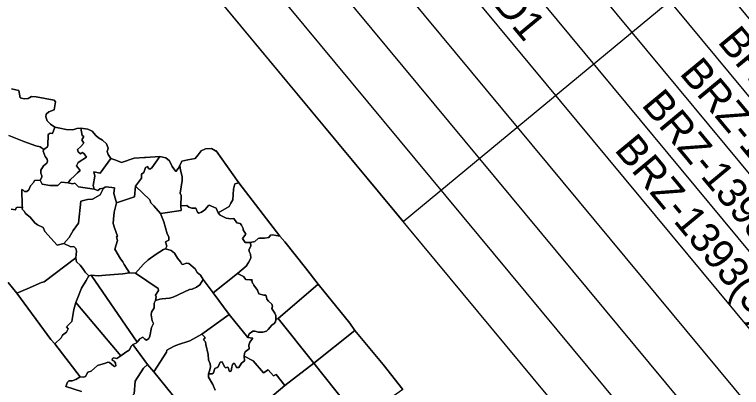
# Model space of a CAD drawing. Extents: x 2054826 to 2060231, y 685508 to 690809.
# Drawn here: x 2059671.1 to 2059946.5, y 688368.3 to 688509.7 of the extents above; entities that cross this region are included whole.
import ezdxf

# ---------------------------------------------------------------- set-up
doc = ezdxf.new("R2010")
doc.units = 0
for name, color, linetype in [('Old_Level_1', 7, 'Continuous'), ('Sheet Data Field CELL', 7, 'Continuous'), ('Sheet Title CELL', 7, 'Continuous')]:
    doc.layers.add(name, color=color, linetype=linetype)

msp = doc.modelspace()

# ---------------------------------------------------------------- linework, layer by layer
at = {"layer": 'Old_Level_1'}
for points in [[(2059818.23, 688367.63), (2059810.84, 688376.99), (2059800.09, 688389.92), (2059798.1, 688392.71), (2059786.18, 688407.48), (2059781.34, 688413.68), (2059773.48, 688423.55), (2059771.69, 688425.65), (2059756.11, 688445.98), (2059747.56, 688458.07), (2059747.29, 688458.09), (2059745.8, 688458.95), (2059743.52, 688458.8), (2059741.81, 688458.03), (2059740.71, 688456.55), (2059739.52, 688455.21), (2059736.76, 688454.59), (2059734.58, 688454.14), (2059733.76, 688452.5), (2059733.12, 688451.4), (2059732.19, 688450.21), (2059730.88, 688452.06), (2059729.91, 688454.21), (2059728.48, 688455.38), (2059726.15, 688455.9), (2059720.72, 688455.49), (2059720.35, 688455.53), (2059716.49, 688455.28), (2059711.71, 688453.68), (2059709.46, 688454.5), (2059707.59, 688455.12), (2059706.58, 688456.62), (2059706.3, 688457.77), (2059706.64, 688459.04), (2059706.04, 688460.71), (2059704.46, 688462.12), (2059702.91, 688462.94), (2059701.94, 688463.93), (2059700.61, 688465.5), (2059698.89, 688466.29), (2059696.2, 688466.66), (2059694.77, 688466.58), (2059693.19, 688466.03), (2059690.67, 688466.15), (2059688.34, 688466.66), (2059686.47, 688467), (2059684.74, 688468.22), (2059683.51, 688469.49), (2059682.96, 688470.92), (2059683.15, 688472.01), (2059684.14, 688472.8), (2059686.22, 688473.66), (2059686.61, 688476.66), (2059686.21, 688477.29), (2059679.29, 688478.55), (2059677.54, 688478.69), (2059676.28, 688477.91), (2059674.83, 688477.71), (2059673.31, 688478.18), (2059672.72, 688480.91), (2059671.59, 688481.18), (2059670, 688481.6)], [(2059670, 688481.6), (2059671.59, 688481.18), (2059672.72, 688480.91), (2059673.31, 688478.18), (2059674.83, 688477.71), (2059676.28, 688477.91), (2059677.54, 688478.69), (2059679.29, 688478.55)], [(2059679.29, 688478.55), (2059686.21, 688477.29), (2059686.61, 688476.66), (2059686.22, 688473.66), (2059684.14, 688472.8), (2059683.15, 688472.01), (2059682.96, 688470.92), (2059683.51, 688469.49), (2059684.74, 688468.22), (2059686.47, 688467), (2059685.57, 688464.67), (2059684.62, 688464.79), (2059683.95, 688464.19), (2059683.8, 688460.12), (2059683.62, 688459.57), (2059682.19, 688458.5), (2059680.91, 688459.56), (2059679.21, 688459.92), (2059674.73, 688461.63), (2059668.93, 688463.93)], [(2059696.2, 688466.66), (2059696.78, 688463.92), (2059697.46, 688463.54), (2059696.68, 688462.27), (2059697.41, 688460.95), (2059696.12, 688459.53), (2059695.01, 688458.5), (2059695.3, 688457.62), (2059696.13, 688456.98), (2059696.93, 688457.39), (2059697.58, 688456.9), (2059698.38, 688455.62), (2059695.23, 688453.68), (2059694.66, 688452.36), (2059696.06, 688450.66), (2059694.98, 688449.73), (2059693.9, 688448.53), (2059692.4, 688447.17), (2059691.41, 688445.95), (2059688.86, 688446.14), (2059687.49, 688444.85), (2059684.52, 688444.86), (2059681.67, 688445.39), (2059680.82, 688446.89), (2059681.53, 688448.13), (2059681.48, 688448.62), (2059681.11, 688449.63), (2059681.1, 688450.77), (2059682.07, 688452.42), (2059683.41, 688453.34), (2059683.59, 688454.17), (2059683.55, 688454.93), (2059682.79, 688455.87), (2059682.05, 688457.89), (2059682.19, 688458.5), (2059683.62, 688459.57), (2059683.8, 688460.12), (2059683.95, 688464.19), (2059684.62, 688464.79), (2059685.57, 688464.67), (2059686.47, 688467), (2059688.34, 688466.66), (2059690.67, 688466.15), (2059693.19, 688466.03), (2059694.77, 688466.58), (2059696.2, 688466.66)], [(2059701.26, 688443.55), (2059695.44, 688444.37), (2059694.03, 688445.8), (2059693.16, 688445.52), (2059691.41, 688445.95), (2059692.4, 688447.17), (2059693.9, 688448.53), (2059694.98, 688449.73), (2059696.06, 688450.66), (2059694.66, 688452.36), (2059695.23, 688453.68), (2059698.38, 688455.62), (2059697.58, 688456.9), (2059696.93, 688457.39), (2059696.13, 688456.98), (2059695.3, 688457.62), (2059695.01, 688458.5), (2059696.12, 688459.53), (2059697.41, 688460.95), (2059696.68, 688462.27), (2059697.46, 688463.54), (2059696.78, 688463.92), (2059696.2, 688466.66), (2059698.89, 688466.29), (2059700.61, 688465.5), (2059701.94, 688463.93), (2059702.91, 688462.94), (2059704.46, 688462.12), (2059706.04, 688460.71), (2059706.64, 688459.04), (2059706.3, 688457.77), (2059706.58, 688456.62), (2059707.59, 688455.12), (2059703.58, 688449.65), (2059701.13, 688450.08), (2059701.58, 688448.51), (2059700.97, 688444.86), (2059701.26, 688443.55)], [(2059668.93, 688463.93), (2059674.73, 688461.63), (2059679.21, 688459.92), (2059680.91, 688459.56)], [(2059680.91, 688459.56), (2059682.19, 688458.5), (2059682.05, 688457.89), (2059682.79, 688455.87), (2059683.55, 688454.93), (2059683.59, 688454.17), (2059683.41, 688453.34), (2059682.07, 688452.42), (2059681.1, 688450.77), (2059681.11, 688449.63), (2059681.48, 688448.62), (2059681.53, 688448.13), (2059680.82, 688446.89), (2059678.74, 688446.75), (2059678.45, 688446.22), (2059677.23, 688444.84), (2059676.59, 688443.22), (2059675.86, 688442.59), (2059674.95, 688442.64), (2059674.43, 688443.2), (2059673.88, 688443.39), (2059674.01, 688437.32), (2059674.22, 688436.57), (2059672.21, 688436.73), (2059671.81, 688436.4), (2059671.49, 688435.67), (2059669.87, 688435.9)], [(2059756.11, 688445.98), (2059754.64, 688445.53), (2059754.15, 688443.47), (2059753.81, 688439.46), (2059753.11, 688438.16), (2059752.49, 688436.89), (2059748.33, 688434.56), (2059747.5, 688436.35), (2059744.92, 688437.44), (2059744.56, 688437.31), (2059743.2, 688435.69), (2059741.94, 688434.76), (2059740.93, 688434.4), (2059740.47, 688434.74), (2059739.81, 688436.38), (2059738.32, 688436.26), (2059737.21, 688436.65), (2059736.44, 688437.33), (2059734.17, 688437.19), (2059734.28, 688441.14), (2059733.87, 688441.95), (2059734.66, 688446.76), (2059734.65, 688448.35), (2059733.96, 688450.76), (2059733.76, 688452.5), (2059734.58, 688454.14), (2059736.76, 688454.59), (2059739.52, 688455.21), (2059740.71, 688456.55), (2059741.81, 688458.03), (2059743.52, 688458.8), (2059745.8, 688458.95), (2059747.29, 688458.09), (2059747.56, 688458.07), (2059756.11, 688445.98)], [(2059717.03, 688444.66), (2059716.54, 688440.65), (2059709.77, 688438.37), (2059708.96, 688440.95), (2059708.8, 688441.91), (2059709.03, 688444.08), (2059705.92, 688444.46), (2059705.54, 688444.23), (2059704.87, 688443.91), (2059703.52, 688443.7), (2059702.65, 688442.99), (2059701.26, 688443.55), (2059700.97, 688444.86), (2059701.58, 688448.51), (2059701.13, 688450.08), (2059703.58, 688449.65), (2059707.59, 688455.12), (2059709.46, 688454.5), (2059711.71, 688453.68), (2059716.49, 688455.28), (2059720.35, 688455.53), (2059720.72, 688455.49), (2059726.15, 688455.9), (2059723.1, 688451.64), (2059722.42, 688451.05), (2059721.75, 688451.43), (2059721.62, 688452.06), (2059720.74, 688451.79), (2059720.09, 688449.88), (2059719.22, 688449.18), (2059719.19, 688447.66), (2059717.03, 688444.66)], [(2059733.76, 688452.5), (2059733.96, 688450.76), (2059734.65, 688448.35), (2059734.66, 688446.76), (2059733.87, 688441.95), (2059734.28, 688441.14), (2059734.17, 688437.19), (2059734.26, 688435.48), (2059726.47, 688434.28), (2059723.96, 688437.24), (2059722.81, 688438.39), (2059722.41, 688439.47), (2059717.03, 688444.66), (2059719.19, 688447.66), (2059719.22, 688449.18), (2059720.09, 688449.88), (2059720.74, 688451.79), (2059721.62, 688452.06), (2059721.75, 688451.43), (2059722.42, 688451.05), (2059723.1, 688451.64), (2059726.15, 688455.9), (2059728.48, 688455.38), (2059729.91, 688454.21), (2059730.88, 688452.06), (2059732.19, 688450.21), (2059733.12, 688451.4), (2059733.76, 688452.5)], [(2059703.52, 688443.7), (2059704.87, 688443.91), (2059703.64, 688441.39), (2059700.66, 688439.74), (2059698.84, 688439.59), (2059696.2, 688438.94), (2059695.32, 688430.67), (2059693.37, 688427.8), (2059691.85, 688425.2), (2059689.77, 688422.96), (2059687.34, 688422.27), (2059682.62, 688427.52), (2059682.04, 688429.01), (2059679.89, 688429.97), (2059678.84, 688430.82), (2059677.05, 688432.87), (2059675.31, 688434.26), (2059674.82, 688435.18), (2059674.08, 688435.95), (2059674.22, 688436.57), (2059674.01, 688437.32), (2059673.88, 688443.39), (2059674.43, 688443.2), (2059674.95, 688442.64), (2059675.86, 688442.59), (2059676.59, 688443.22), (2059677.23, 688444.84), (2059678.45, 688446.22), (2059678.74, 688446.75), (2059680.82, 688446.89), (2059681.67, 688445.39), (2059684.52, 688444.86), (2059687.49, 688444.85), (2059688.86, 688446.14), (2059691.41, 688445.95), (2059693.16, 688445.52), (2059694.03, 688445.8), (2059695.44, 688444.37), (2059701.26, 688443.55), (2059702.65, 688442.99), (2059703.52, 688443.7)], [(2059709.77, 688438.37), (2059708.9, 688434.84), (2059708.66, 688432.14), (2059708.5, 688430.55), (2059708.99, 688428.91), (2059710.13, 688425.65), (2059709.81, 688425.46), (2059710.14, 688424.08), (2059709.08, 688420.72), (2059711.28, 688417.14), (2059712.19, 688415.93), (2059712.65, 688414.9), (2059713.8, 688413.15), (2059714.73, 688411.78), (2059712.2, 688411.39), (2059705.59, 688410.88), (2059702.84, 688410.7), (2059700.2, 688410.93), (2059699.32, 688410.66), (2059697.86, 688412.05), (2059697.28, 688413.01), (2059695.96, 688414.74), (2059694.61, 688415.94), (2059694.33, 688417.52), (2059694.59, 688420.04), (2059694.4, 688421.06), (2059693.64, 688421.74), (2059692.42, 688421.61), (2059689.77, 688422.96), (2059691.85, 688425.2), (2059693.37, 688427.8), (2059695.32, 688430.67), (2059696.2, 688438.94), (2059698.84, 688439.59), (2059700.66, 688439.74), (2059703.64, 688441.39), (2059704.87, 688443.91), (2059705.54, 688444.23), (2059705.92, 688444.46), (2059709.03, 688444.08), (2059708.8, 688441.91), (2059708.96, 688440.95), (2059709.77, 688438.37)], [(2059716.97, 688411.65), (2059714.73, 688411.78), (2059713.8, 688413.15), (2059712.65, 688414.9), (2059712.19, 688415.93), (2059711.28, 688417.14), (2059709.08, 688420.72), (2059710.14, 688424.08), (2059709.81, 688425.46), (2059710.13, 688425.65), (2059708.99, 688428.91), (2059708.5, 688430.55), (2059708.66, 688432.14), (2059708.9, 688434.84), (2059709.77, 688438.37), (2059716.54, 688440.65), (2059717.03, 688444.66), (2059722.41, 688439.47), (2059722.81, 688438.39), (2059723.96, 688437.24), (2059726.47, 688434.28), (2059727.76, 688431.18), (2059728.91, 688426.6), (2059729.58, 688425.51), (2059729.64, 688424.14), (2059728.31, 688423.6), (2059728.79, 688421.96), (2059728.32, 688420.88), (2059727.57, 688420.69), (2059724.8, 688418.84), (2059721.75, 688416.73), (2059720.06, 688415.09), (2059716.97, 688411.65)], [(2059771.69, 688425.65), (2059768.81, 688426.23), (2059768.06, 688426.03), (2059767.42, 688425.21), (2059765.83, 688424.97), (2059763.98, 688425), (2059763.43, 688424.76), (2059762.18, 688423.66), (2059760.56, 688423.31), (2059758.49, 688423.3), (2059757.44, 688424.87), (2059758.81, 688426.49), (2059757.77, 688428.07), (2059757.79, 688428.61), (2059757.11, 688429.88), (2059756.59, 688430.45), (2059755.39, 688430.7), (2059754.16, 688432.43), (2059753.04, 688432.28), (2059751.36, 688432.59), (2059749.05, 688433.67), (2059748.33, 688434.56), (2059752.49, 688436.89), (2059753.11, 688438.16), (2059753.81, 688439.46), (2059754.15, 688443.47), (2059754.64, 688445.53), (2059756.11, 688445.98), (2059771.69, 688425.65)], [(2059669.87, 688435.9), (2059671.49, 688435.67), (2059671.81, 688436.4), (2059672.21, 688436.73), (2059674.22, 688436.57), (2059674.08, 688435.95), (2059674.82, 688435.18), (2059675.31, 688434.26), (2059677.05, 688432.87), (2059678.84, 688430.82), (2059679.89, 688429.97), (2059682.04, 688429.01), (2059682.62, 688427.52), (2059687.34, 688422.27), (2059689.77, 688422.96), (2059692.42, 688421.61), (2059693.64, 688421.74), (2059694.4, 688421.06), (2059694.59, 688420.04), (2059694.33, 688417.52)], [(2059760.56, 688423.31), (2059760.68, 688421.97), (2059759.94, 688420.47), (2059760.18, 688419.64), (2059760.58, 688418.83), (2059760.61, 688417.34), (2059759.78, 688415.7), (2059758.85, 688414.36), (2059755.67, 688411.58), (2059746.38, 688404.27), (2059742.58, 688409.27), (2059741.63, 688410.98), (2059740.34, 688411.97), (2059739.62, 688413.29), (2059737.13, 688415.39), (2059736.29, 688415.49), (2059734.9, 688414.93), (2059734.55, 688415.06), (2059734.07, 688416.01), (2059732.92, 688417.33), (2059731.74, 688419.26), (2059730.52, 688420.27), (2059728.32, 688420.88), (2059728.79, 688421.96), (2059728.31, 688423.6), (2059729.64, 688424.14), (2059729.58, 688425.51), (2059728.91, 688426.6), (2059727.76, 688431.18), (2059726.47, 688434.28), (2059734.26, 688435.48), (2059734.17, 688437.19), (2059736.44, 688437.33), (2059737.21, 688436.65), (2059738.32, 688436.26), (2059739.81, 688436.38), (2059740.47, 688434.74), (2059740.93, 688434.4), (2059741.94, 688434.76), (2059743.2, 688435.69), (2059744.56, 688437.31), (2059744.92, 688437.44), (2059747.5, 688436.35), (2059748.33, 688434.56), (2059749.05, 688433.67), (2059751.36, 688432.59), (2059753.04, 688432.28), (2059754.16, 688432.43), (2059755.39, 688430.7), (2059756.59, 688430.45), (2059757.11, 688429.88), (2059757.79, 688428.61), (2059757.77, 688428.07), (2059758.81, 688426.49), (2059757.44, 688424.87), (2059758.49, 688423.3), (2059760.56, 688423.31)], [(2059771.05, 688394.49), (2059770.14, 688394.13), (2059770.19, 688395.64), (2059769.81, 688396.56), (2059768.98, 688397.65), (2059768.66, 688398.34), (2059768.82, 688399.22), (2059768.56, 688399.94), (2059767.36, 688401.07), (2059766.77, 688401.77), (2059766.54, 688402.6), (2059766.28, 688403.32), (2059765.64, 688403.38), (2059763.66, 688403.79), (2059763.13, 688405.23), (2059761.8, 688407.16), (2059761.53, 688407.61), (2059761.33, 688407.93), (2059761.06, 688408.82), (2059761.13, 688409.13), (2059760.26, 688409.14), (2059758.71, 688409.27), (2059757.84, 688410.41), (2059755.67, 688411.58), (2059758.85, 688414.36), (2059759.78, 688415.7), (2059760.61, 688417.34), (2059760.58, 688418.83), (2059760.18, 688419.64), (2059759.94, 688420.47), (2059760.68, 688421.97), (2059760.56, 688423.31), (2059762.18, 688423.66), (2059763.43, 688424.76), (2059763.98, 688425), (2059765.83, 688424.97), (2059767.42, 688425.21), (2059768.06, 688426.03), (2059768.81, 688426.23), (2059771.69, 688425.65), (2059773.48, 688423.55), (2059781.34, 688413.68), (2059786.18, 688407.48), (2059771.05, 688394.49)], [(2059742.58, 688409.27), (2059741.28, 688407.27), (2059740.09, 688406.38), (2059738.45, 688405.66), (2059737.39, 688405.54), (2059731.24, 688402.56), (2059729.8, 688402.22), (2059727.09, 688401.99), (2059726.13, 688401.85), (2059724.59, 688401.27), (2059724.76, 688402.69), (2059724.6, 688403.38), (2059725.65, 688405.06), (2059725.52, 688405.85), (2059716.97, 688411.65), (2059720.06, 688415.09), (2059721.75, 688416.73), (2059724.8, 688418.84), (2059727.57, 688420.69), (2059728.32, 688420.88), (2059730.52, 688420.27), (2059731.74, 688419.26), (2059732.92, 688417.33), (2059734.07, 688416.01), (2059734.55, 688415.06), (2059734.9, 688414.93), (2059736.29, 688415.49), (2059737.13, 688415.39), (2059739.62, 688413.29), (2059740.34, 688411.97), (2059741.63, 688410.98), (2059742.58, 688409.27)], [(2059694.33, 688417.52), (2059682.4, 688408.4), (2059681.3, 688408.08), (2059675.96, 688405.69), (2059671.98, 688404.04), (2059668.79, 688408.1)], [(2059699.32, 688410.66), (2059698.22, 688408.94), (2059696.46, 688406.03), (2059695.09, 688402.5), (2059694.43, 688400.61), (2059693.64, 688397.96), (2059692.86, 688393.31), (2059692.19, 688392.72), (2059690.89, 688391.32), (2059691.52, 688390.57), (2059690.78, 688389.25), (2059689.32, 688388.12), (2059688.78, 688387.18), (2059686.46, 688384.91), (2059684.96, 688386.52), (2059671.98, 688404.04), (2059675.96, 688405.69), (2059681.3, 688408.08), (2059682.4, 688408.4), (2059694.33, 688417.52), (2059694.61, 688415.94), (2059695.96, 688414.74), (2059697.28, 688413.01), (2059697.86, 688412.05), (2059699.32, 688410.66)], [(2059700.2, 688410.93), (2059717.56, 688385.53), (2059717.2, 688385.13), (2059715.98, 688384.58), (2059715.43, 688384.08), (2059714.56, 688382.52), (2059713.34, 688381.7), (2059711.4, 688380.36), (2059694.43, 688400.61), (2059695.09, 688402.5), (2059696.46, 688406.03), (2059698.22, 688408.94), (2059699.32, 688410.66), (2059700.2, 688410.93)], [(2059716.97, 688411.65), (2059725.52, 688405.85), (2059725.65, 688405.06), (2059724.6, 688403.38), (2059724.76, 688402.69), (2059724.59, 688401.27), (2059724.04, 688400.32), (2059723.99, 688398.55), (2059723, 688396.91), (2059722.96, 688395.83), (2059723.22, 688393.55), (2059723.74, 688392.55), (2059723.07, 688391.1), (2059722.38, 688387.81), (2059722.06, 688386.92), (2059721.19, 688386.22), (2059720.49, 688386.67), (2059719.73, 688387.35), (2059718.56, 688386.73), (2059717.56, 688385.53), (2059700.2, 688410.93), (2059702.84, 688410.7), (2059705.59, 688410.88), (2059712.2, 688411.39), (2059714.73, 688411.78), (2059716.97, 688411.65)], [(2059768.56, 688399.94), (2059768.82, 688399.22), (2059768.66, 688398.34), (2059768.98, 688397.65), (2059769.81, 688396.56), (2059770.19, 688395.64), (2059770.14, 688394.13), (2059770.01, 688393.18), (2059769.53, 688392.54), (2059768.57, 688391.97), (2059767.2, 688390.37), (2059766.65, 688389.69), (2059765.18, 688389.26), (2059763.54, 688389.25), (2059762.13, 688389.74), (2059761.4, 688389.65), (2059760.01, 688388.65), (2059759.52, 688387.31), (2059752.49, 688396), (2059746.38, 688404.27), (2059755.67, 688411.58), (2059757.84, 688410.41), (2059758.71, 688409.27), (2059760.26, 688409.14), (2059761.13, 688409.13), (2059761.06, 688408.82), (2059761.33, 688407.93), (2059761.53, 688407.61), (2059761.8, 688407.16), (2059763.13, 688405.23), (2059763.66, 688403.79), (2059765.64, 688403.38), (2059766.28, 688403.32), (2059766.54, 688402.6), (2059766.77, 688401.77), (2059767.36, 688401.07), (2059768.56, 688399.94)], [(2059668.79, 688408.1), (2059671.98, 688404.04), (2059684.96, 688386.52), (2059686.46, 688384.91), (2059696.06, 688372.37), (2059694.32, 688371.41), (2059692.95, 688370.85), (2059691.76, 688370.83), (2059691.15, 688370.29), (2059690.59, 688368.66), (2059696.53, 688366.76)], [(2059742.13, 688388.52), (2059737.57, 688386.07), (2059732.91, 688384.51), (2059731.36, 688383.93), (2059728.78, 688382.48), (2059728.72, 688381.74), (2059723.86, 688374.24), (2059721.5, 688377.01), (2059715.98, 688384.58), (2059717.2, 688385.13), (2059717.56, 688385.53), (2059718.56, 688386.73), (2059719.73, 688387.35), (2059720.49, 688386.67), (2059721.19, 688386.22), (2059722.06, 688386.92), (2059722.38, 688387.81), (2059723.07, 688391.1), (2059723.74, 688392.55), (2059723.22, 688393.55), (2059722.96, 688395.83), (2059723, 688396.91), (2059723.99, 688398.55), (2059724.04, 688400.32), (2059724.59, 688401.27), (2059726.13, 688401.85), (2059727.09, 688401.99), (2059729.8, 688402.22), (2059731.24, 688402.56), (2059737.39, 688405.54), (2059738.45, 688405.66), (2059740.09, 688406.38), (2059741.28, 688407.27), (2059742.58, 688409.27), (2059746.38, 688404.27), (2059752.49, 688396), (2059742.13, 688388.52)], [(2059800.09, 688389.92), (2059784.57, 688377.59), (2059771.05, 688394.49), (2059786.18, 688407.48), (2059798.1, 688392.71), (2059800.09, 688389.92)], [(2059711.4, 688380.36), (2059709.86, 688379.35), (2059708.72, 688379.53), (2059708.24, 688379.33), (2059708.09, 688378.72), (2059708.92, 688378.35), (2059709.38, 688377.58), (2059709.51, 688376.53), (2059709.07, 688376.26), (2059708.58, 688376.5), (2059707.17, 688377.82), (2059706.44, 688377.91), (2059705.61, 688377.58), (2059702.57, 688376.63), (2059700.14, 688374.56), (2059698.95, 688374.11), (2059698.09, 688372.55), (2059697.22, 688372.29), (2059696.06, 688372.37), (2059686.46, 688384.91), (2059688.78, 688387.18), (2059689.32, 688388.12), (2059690.78, 688389.25), (2059691.52, 688390.57), (2059690.89, 688391.32), (2059692.19, 688392.72), (2059692.86, 688393.31), (2059693.64, 688397.96), (2059694.43, 688400.61), (2059711.4, 688380.36)], [(2059761.41, 688387.03), (2059760.29, 688385.58), (2059759.92, 688384.32), (2059759.97, 688382.95), (2059758.49, 688381.81), (2059758.24, 688381.23), (2059758.19, 688380.15), (2059758.26, 688378.44), (2059757.16, 688377.53), (2059756.12, 688375.96), (2059755.25, 688375.97), (2059754.59, 688377.24), (2059754.29, 688377.58), (2059753.73, 688377.08), (2059753.48, 688376.06), (2059753.23, 688374.6), (2059752.79, 688374.34), (2059752.42, 688374.65), (2059752.09, 688375.93), (2059751.78, 688376.01), (2059751.07, 688375.77), (2059750.63, 688376.2), (2059749.85, 688378.09), (2059749.1, 688377.91), (2059748.3, 688376.22), (2059747.86, 688375.95), (2059746.99, 688375.53), (2059746.49, 688373.93), (2059746.05, 688373.5), (2059744.59, 688373.5), (2059745.17, 688374.98), (2059745.41, 688376.16), (2059745.21, 688377.35), (2059744.56, 688378.88), (2059744.5, 688380.85), (2059743.62, 688384.61), (2059743.5, 688385.67), (2059742.71, 688386.42), (2059743.4, 688387.27), (2059742.13, 688388.52), (2059752.49, 688396), (2059759.52, 688387.31), (2059760.46, 688387.17), (2059761.41, 688387.03)], [(2059771.05, 688394.49), (2059784.57, 688377.59), (2059773.57, 688369.05), (2059770.21, 688373.27), (2059769.25, 688372.71), (2059767.17, 688375.06), (2059765.46, 688373.88), (2059761.59, 688378.49), (2059758.19, 688380.15), (2059758.24, 688381.23), (2059758.49, 688381.81), (2059759.97, 688382.95), (2059759.92, 688384.32), (2059760.29, 688385.58), (2059761.41, 688387.03), (2059760.46, 688387.17), (2059759.52, 688387.31), (2059760.01, 688388.65), (2059761.4, 688389.65), (2059762.13, 688389.74), (2059763.54, 688389.25), (2059765.18, 688389.26), (2059766.65, 688389.69), (2059767.2, 688390.37), (2059768.57, 688391.97), (2059769.53, 688392.54), (2059770.01, 688393.18), (2059770.14, 688394.13), (2059771.05, 688394.49)], [(2059810.84, 688376.99), (2059818.23, 688367.63), (2059801.69, 688355.96), (2059784.57, 688377.59), (2059800.09, 688389.92), (2059810.84, 688376.99)], [(2059737.78, 688357.14), (2059723.86, 688374.24), (2059728.72, 688381.74), (2059728.78, 688382.48), (2059731.36, 688383.93), (2059732.91, 688384.51), (2059737.57, 688386.07), (2059742.13, 688388.52), (2059743.4, 688387.27)], [(2059743.4, 688387.27), (2059742.71, 688386.42), (2059743.5, 688385.67), (2059743.62, 688384.61), (2059744.5, 688380.85), (2059744.56, 688378.88), (2059745.21, 688377.35), (2059745.41, 688376.16), (2059745.17, 688374.98), (2059744.59, 688373.5), (2059744.66, 688372.24), (2059746.25, 688369.43), (2059747.14, 688367.35)], [(2059696.53, 688366.76), (2059690.59, 688368.66), (2059691.15, 688370.29), (2059691.76, 688370.83), (2059692.95, 688370.85), (2059694.32, 688371.41), (2059696.06, 688372.37), (2059697.22, 688372.29), (2059698.09, 688372.55), (2059698.95, 688374.11), (2059700.14, 688374.56), (2059702.57, 688376.63), (2059705.61, 688377.58), (2059706.44, 688377.91), (2059707.17, 688377.82), (2059708.58, 688376.5), (2059709.07, 688376.26), (2059709.51, 688376.53), (2059709.38, 688377.58), (2059708.92, 688378.35), (2059708.09, 688378.72), (2059708.24, 688379.33), (2059708.72, 688379.53), (2059709.86, 688379.35), (2059711.4, 688380.36), (2059713.34, 688381.7), (2059714.56, 688382.52), (2059715.43, 688384.08), (2059715.98, 688384.58)], [(2059715.98, 688384.58), (2059721.5, 688377.01), (2059719.99, 688375.67), (2059716.79, 688370.72), (2059716.52, 688365.87)], [(2059747.14, 688367.35), (2059746.25, 688369.43), (2059744.66, 688372.24), (2059744.59, 688373.5), (2059746.05, 688373.5), (2059746.49, 688373.93), (2059746.99, 688375.53), (2059747.86, 688375.95), (2059748.3, 688376.22), (2059749.1, 688377.91), (2059749.85, 688378.09), (2059750.63, 688376.2), (2059751.07, 688375.77), (2059751.78, 688376.01), (2059752.09, 688375.93), (2059752.42, 688374.65), (2059752.79, 688374.34), (2059753.23, 688374.6), (2059753.48, 688376.06), (2059753.73, 688377.08), (2059754.29, 688377.58), (2059754.59, 688377.24), (2059755.25, 688375.97), (2059756.12, 688375.96), (2059757.16, 688377.53), (2059758.26, 688378.44), (2059758.19, 688380.15), (2059761.59, 688378.49), (2059765.46, 688373.88), (2059767.17, 688375.06), (2059769.25, 688372.71), (2059770.21, 688373.27)], [(2059723.86, 688374.24), (2059737.78, 688357.14), (2059714.65, 688352.73), (2059713.29, 688355.29), (2059713.02, 688360.15), (2059713.07, 688362.08), (2059716.52, 688365.87), (2059716.79, 688370.72), (2059719.99, 688375.67), (2059721.5, 688377.01), (2059723.86, 688374.24)], [(2059801.69, 688355.96), (2059787.99, 688345.87), (2059783.66, 688342.58), (2059767.11, 688363.7), (2059773.57, 688369.05), (2059784.57, 688377.59), (2059801.69, 688355.96)], [(2059770.21, 688373.27), (2059773.57, 688369.05), (2059767.11, 688363.7)]]:
    msp.add_lwpolyline(points, dxfattribs=at)
at = {"layer": 'Sheet Title CELL'}
for points in [[(2060167.11, 688363.15), (2059903.79, 688680.66), (2059730.61, 688537.05), (2059818.34, 688431.22), (2059948.24, 688538.93), (2059896.39, 688601.46), (2059939.71, 688637.38), (2060095.3, 688449.72)], [(2060094.93, 688303.29), (2059831.62, 688620.82), (2059846.06, 688632.79), (2060109.37, 688315.26)], [(2060066.08, 688279.37), (2059802.77, 688596.89), (2059817.19, 688608.85), (2060080.51, 688291.33)], [(2060037.2, 688255.42), (2059773.9, 688572.93), (2059788.34, 688584.93), (2060051.65, 688267.4)], [(2060008.33, 688231.48), (2059745.04, 688549.02), (2059759.46, 688560.98), (2060022.77, 688243.45)], [(2059730.61, 688537.05), (2059993.92, 688219.52)]]:
    msp.add_lwpolyline(points, dxfattribs=at)

# ---------------------------------------------------------------- texts
at = {"layer": 'Sheet Data Field CELL'}
for s, p in [('38456.3.FD1', (2059808.92, 688565.86)), ('BRZ-1393(3)   ', (2059937.18, 688499.29)), ('BRZ-1393(3)   ', (2059922.74, 688487.32)), ('BRZ-1393(3)   ', (2059908.32, 688475.36)), ('BRZ-1393(3)', (2059898.07, 688458.36))]:
    msp.add_text(s, height=11.25, rotation=309.6672, dxfattribs=at).set_placement(p)

doc.saveas('drawing.dxf')
